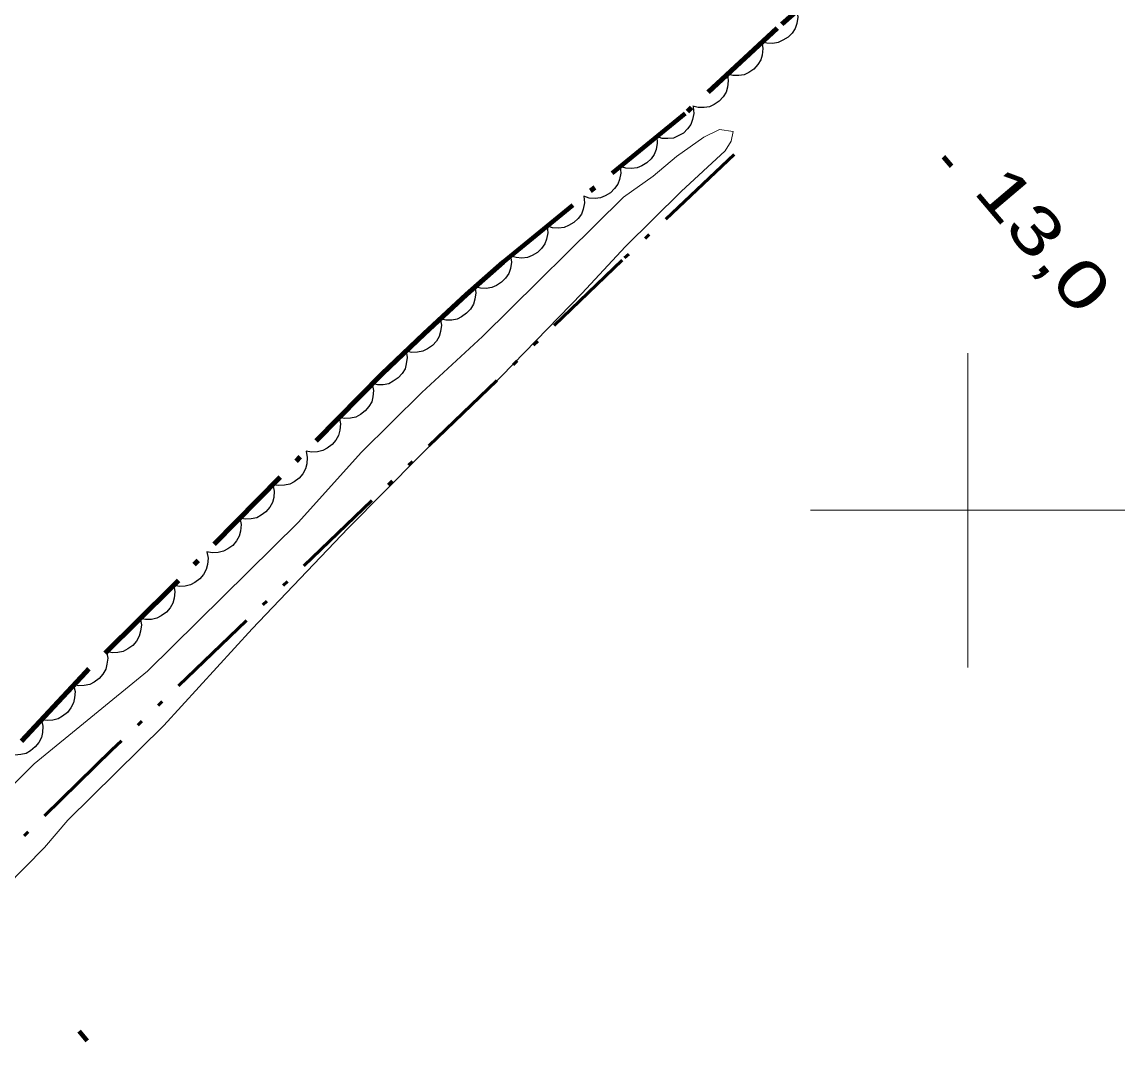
# Model space of a CAD drawing. Extents: x 386081 to 389416, y 5130568 to 5134082.
# Drawn here: x 387339.8 to 387410, y 5132366 to 5132431.1 of the extents above; entities that cross this region are included whole.
import ezdxf

# ---------------------------------------------------------------- set-up
doc = ezdxf.new("R2010")
doc.units = 0
doc.header["$LTSCALE"] = 1.2
doc.linetypes.add('DASH_DOUBLE_DOT', pattern=[9.2, 5, -1.2, 0.3, -1.2, 0.3, -1.2])
doc.linetypes.add('DOT_DASHED', pattern=[7.7, 5, -1.2, 0.3, -1.2])
for name, color, linetype, lineweight in [('2', 7, 'Continuous', 13), ('3', 7, 'Continuous', 140), ('4', 7, 'DASH_DOUBLE_DOT', 53), ('44', 7, 'Continuous', 25), ('61', 7, 'Continuous', 13)]:
    doc.layers.add(name, color=color, linetype=linetype, lineweight=lineweight)

msp = doc.modelspace()

# ---------------------------------------------------------------- linework, layer by layer
at = {"layer": '2'}
msp.add_lwpolyline([(387336.85, 5132380.17), (387340.59, 5132383.86), (387347.81, 5132389.76), (387357.4, 5132399.24), (387361.4, 5132403.67), (387365.26, 5132407.49), (387369.12, 5132411.06), (387378.1, 5132419.92), (387379.97, 5132421.27), (387381.46, 5132422.51), (387383.2, 5132423.74), (387384.2, 5132424.23), (387385.06, 5132424.1), (387384.94, 5132423.48), (387384.56, 5132422.87), (387381.75, 5132420.28), (387378.2, 5132416.77), (387375.46, 5132413.82), (387369.59, 5132407.78), (387367.41, 5132405.75), (387360.56, 5132398.86), (387354.45, 5132392.46), (387348.84, 5132386.3), (387342.73, 5132380.28), (387341.24, 5132378.55), (387337.5, 5132374.74)], dxfattribs=at)
at = {"layer": '3'}
for p, q in [((387398.45, 5132422.5), (387398.96, 5132421.89)), ((387343.46, 5132366.85), (387343.97, 5132366.24))]:
    msp.add_line(p, q, dxfattribs=at)
at = {"layer": '4'}
msp.add_lwpolyline([(387385.14, 5132422.65), (387378, 5132415.91), (387345.53, 5132384.75), (387338.02, 5132377.4), (387332.95, 5132371.44), (387328.66, 5132365.36), (387323.45, 5132358.88), (387320.1, 5132355.51), (387317.98, 5132352.68), (387317.57, 5132352.26), (387316.14, 5132350.32), (387313.69, 5132346.48), (387308.47, 5132338.84), (387304.07, 5132332.7)], dxfattribs=at)
at = {"layer": '44', "linetype": 'DOT_DASHED', "lineweight": 90}
msp.add_lwpolyline([(387392.66, 5132434.91), (387387.87, 5132430.69), (387382.02, 5132425.26), (387370.43, 5132415.78), (387368.09, 5132413.74), (387365.41, 5132411.23), (387362.74, 5132408.69), (387349.37, 5132395.13), (387343.87, 5132389.71), (387337.32, 5132382.66)], dxfattribs=at)
at = {"layer": '44'}
for points in [[(387389.13, 5132431.8), (387389.18, 5132431.38), (387389.11, 5132430.98), (387389.01, 5132430.67), (387388.82, 5132430.37), (387388.56, 5132430.11), (387388.24, 5132429.91), (387387.94, 5132429.76), (387387.6, 5132429.71), (387387.22, 5132429.72), (387386.88, 5132429.81)], [(387386.9, 5132429.79), (387386.96, 5132429.38), (387386.91, 5132428.97), (387386.82, 5132428.66), (387386.63, 5132428.36), (387386.38, 5132428.08), (387386.06, 5132427.87), (387385.77, 5132427.72), (387385.42, 5132427.67), (387385.05, 5132427.67), (387384.7, 5132427.75)], [(387384.7, 5132427.75), (387384.76, 5132427.34), (387384.71, 5132426.93), (387384.62, 5132426.61), (387384.43, 5132426.32), (387384.18, 5132426.04), (387383.86, 5132425.83), (387383.57, 5132425.68), (387383.22, 5132425.63), (387382.85, 5132425.63), (387382.5, 5132425.71)], [(387382.53, 5132425.68), (387382.57, 5132425.26), (387382.48, 5132424.86), (387382.37, 5132424.55), (387382.17, 5132424.27), (387381.9, 5132424.01), (387381.57, 5132423.82), (387381.27, 5132423.69), (387380.92, 5132423.65), (387380.55, 5132423.67), (387380.21, 5132423.78)], [(387380.21, 5132423.78), (387380.24, 5132423.36), (387380.16, 5132422.96), (387380.05, 5132422.65), (387379.85, 5132422.37), (387379.58, 5132422.11), (387379.25, 5132421.92), (387378.95, 5132421.79), (387378.6, 5132421.75), (387378.23, 5132421.77), (387377.88, 5132421.88)], [(387377.88, 5132421.88), (387377.92, 5132421.46), (387377.84, 5132421.06), (387377.73, 5132420.75), (387377.52, 5132420.47), (387377.26, 5132420.21), (387376.93, 5132420.02), (387376.63, 5132419.89), (387376.28, 5132419.85), (387375.91, 5132419.87), (387375.56, 5132419.98)], [(387375.56, 5132419.98), (387375.6, 5132419.56), (387375.52, 5132419.16), (387375.41, 5132418.85), (387375.2, 5132418.57), (387374.94, 5132418.31), (387374.6, 5132418.12), (387374.31, 5132417.99), (387373.96, 5132417.95), (387373.58, 5132417.98), (387373.24, 5132418.08)], [(387373.24, 5132418.08), (387373.28, 5132417.66), (387373.2, 5132417.26), (387373.09, 5132416.95), (387372.88, 5132416.67), (387372.62, 5132416.41), (387372.28, 5132416.22), (387371.98, 5132416.09), (387371.63, 5132416.05), (387371.26, 5132416.08), (387370.92, 5132416.18)], [(387370.9, 5132416.19), (387370.96, 5132415.78), (387370.89, 5132415.38), (387370.79, 5132415.06), (387370.59, 5132414.77), (387370.33, 5132414.51), (387370.01, 5132414.31), (387369.71, 5132414.17), (387369.36, 5132414.12), (387368.99, 5132414.13), (387368.64, 5132414.22)], [(387368.63, 5132414.24), (387368.69, 5132413.83), (387368.64, 5132413.43), (387368.55, 5132413.11), (387368.36, 5132412.81), (387368.11, 5132412.54), (387367.79, 5132412.32), (387367.51, 5132412.17), (387367.16, 5132412.11), (387366.79, 5132412.11), (387366.44, 5132412.19)], [(387366.43, 5132412.2), (387366.5, 5132411.79), (387366.45, 5132411.38), (387366.36, 5132411.07), (387366.18, 5132410.77), (387365.93, 5132410.49), (387365.61, 5132410.27), (387365.32, 5132410.12), (387364.98, 5132410.06), (387364.61, 5132410.05), (387364.26, 5132410.13)], [(387364.26, 5132410.13), (387364.32, 5132409.72), (387364.27, 5132409.32), (387364.19, 5132409), (387364, 5132408.7), (387363.76, 5132408.42), (387363.44, 5132408.21), (387363.15, 5132408.05), (387362.8, 5132407.99), (387362.43, 5132407.99), (387362.08, 5132408.06)], [(387362.1, 5132408.04), (387362.18, 5132407.63), (387362.14, 5132407.23), (387362.07, 5132406.91), (387361.89, 5132406.6), (387361.66, 5132406.32), (387361.35, 5132406.09), (387361.06, 5132405.93), (387360.72, 5132405.86), (387360.35, 5132405.84), (387360, 5132405.91)], [(387360, 5132405.91), (387360.08, 5132405.5), (387360.04, 5132405.09), (387359.96, 5132404.77), (387359.79, 5132404.47), (387359.55, 5132404.18), (387359.24, 5132403.96), (387358.96, 5132403.8), (387358.61, 5132403.72), (387358.24, 5132403.71), (387357.89, 5132403.77)], [(387357.89, 5132403.77), (387357.97, 5132403.36), (387357.93, 5132402.96), (387357.86, 5132402.63), (387357.68, 5132402.33), (387357.45, 5132402.04), (387357.14, 5132401.82), (387356.85, 5132401.66), (387356.51, 5132401.59), (387356.14, 5132401.57), (387355.78, 5132401.63)], [(387355.78, 5132401.63), (387355.87, 5132401.22), (387355.83, 5132400.82), (387355.75, 5132400.5), (387355.58, 5132400.19), (387355.34, 5132399.91), (387355.03, 5132399.68), (387354.75, 5132399.52), (387354.4, 5132399.45), (387354.03, 5132399.43), (387353.68, 5132399.5)], [(387353.68, 5132399.5), (387353.76, 5132399.09), (387353.72, 5132398.68), (387353.64, 5132398.36), (387353.47, 5132398.06), (387353.23, 5132397.77), (387352.92, 5132397.55), (387352.64, 5132397.39), (387352.3, 5132397.31), (387351.92, 5132397.3), (387351.57, 5132397.36)], [(387351.57, 5132397.36), (387351.65, 5132396.95), (387351.61, 5132396.55), (387351.54, 5132396.23), (387351.36, 5132395.92), (387351.13, 5132395.64), (387350.82, 5132395.41), (387350.53, 5132395.25), (387350.19, 5132395.18), (387349.82, 5132395.16), (387349.46, 5132395.23)], [(387349.47, 5132395.22), (387349.54, 5132394.81), (387349.5, 5132394.41), (387349.42, 5132394.09), (387349.24, 5132393.79), (387349, 5132393.51), (387348.68, 5132393.29), (387348.4, 5132393.13), (387348.05, 5132393.06), (387347.68, 5132393.05), (387347.33, 5132393.12)], [(387347.33, 5132393.12), (387347.41, 5132392.71), (387347.36, 5132392.3), (387347.28, 5132391.98), (387347.1, 5132391.68), (387346.86, 5132391.4), (387346.55, 5132391.18), (387346.26, 5132391.02), (387345.92, 5132390.95), (387345.55, 5132390.94), (387345.19, 5132391.01)], [(387345.19, 5132391.01), (387345.27, 5132390.6), (387345.22, 5132390.2), (387345.14, 5132389.88), (387344.96, 5132389.57), (387344.72, 5132389.29), (387344.41, 5132389.07), (387344.12, 5132388.92), (387343.78, 5132388.85), (387343.41, 5132388.84), (387343.06, 5132388.91)], [(387343.09, 5132388.87), (387343.19, 5132388.47), (387343.16, 5132388.06), (387343.09, 5132387.74), (387342.93, 5132387.43), (387342.7, 5132387.13), (387342.4, 5132386.9), (387342.12, 5132386.73), (387341.78, 5132386.65), (387341.41, 5132386.62), (387341.05, 5132386.67)], [(387341.05, 5132386.67), (387341.14, 5132386.27), (387341.12, 5132385.86), (387341.05, 5132385.54), (387340.88, 5132385.23), (387340.66, 5132384.94), (387340.35, 5132384.7), (387340.08, 5132384.53), (387339.73, 5132384.45), (387339.36, 5132384.42), (387339.01, 5132384.48)]]:
    msp.add_lwpolyline(points, dxfattribs=at)
at = {"layer": '61'}
for p, q in [((387400, 5132390), (387400, 5132410)), ((387390, 5132400), (387410, 5132400))]:
    msp.add_line(p, q, dxfattribs=at)

# ---------------------------------------------------------------- texts
at = {"layer": '3', "width": 1.35}
msp.add_text('13,0   ', height=3, rotation=310.294, dxfattribs=at).set_placement((387400.28, 5132420.28))

doc.saveas('drawing.dxf')
